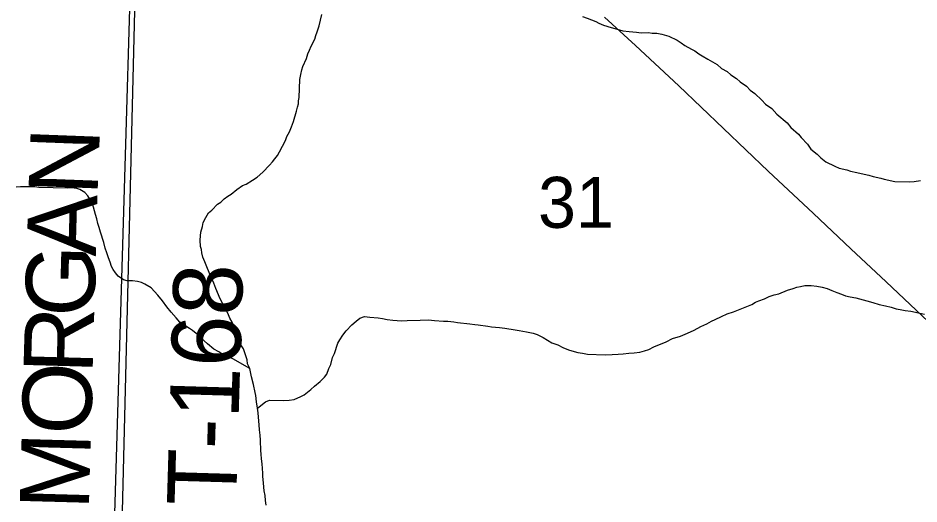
# Model space of a CAD drawing. Extents: x 0 to 34, y -2.3 to 22.
# Drawn here: x 2.383 to 3.123, y 14.692 to 15.091 of the extents above; entities that cross this region are included whole.
import ezdxf

# ---------------------------------------------------------------- set-up
doc = ezdxf.new("R2010")
doc.units = 0
for name, color, linetype in [('GM_X_Minor_River', 7, 'Continuous'), ('GM_X_Section', 7, 'Continuous'), ('GM_X_Section_Text', 7, 'Continuous'), ('GM_X_State_Route', 7, 'Continuous'), ('GM_X_Township', 7, 'Continuous'), ('GM_X_Township_Road', 7, 'Continuous'), ('GM_X_Township_Road_Text', 7, 'Continuous')]:
    doc.layers.add(name, color=color, linetype=linetype)

msp = doc.modelspace()

# ---------------------------------------------------------------- linework, layer by layer
at = {"layer": 'GM_X_Minor_River'}
for p, q in [((2.63081, 15.08452), (2.63298, 15.09395)), ((2.84693, 15.09212), (2.8507, 15.09087)), ((2.8507, 15.09087), (2.85784, 15.088)), ((2.62915, 15.07962), (2.63081, 15.08452)), ((2.85784, 15.088), (2.86046, 15.08678)), ((2.86046, 15.08678), (2.86422, 15.08515)), ((2.86422, 15.08515), (2.87062, 15.08306)), ((2.87062, 15.08306), (2.87741, 15.08133)), ((2.62707, 15.07361), (2.62792, 15.07662)), ((2.62792, 15.07662), (2.62915, 15.07962)), ((2.87741, 15.08133), (2.88005, 15.0805)), ((2.88005, 15.0805), (2.88536, 15.07996)), ((2.88536, 15.07996), (2.89142, 15.0794)), ((2.89142, 15.0794), (2.89521, 15.0789)), ((2.89521, 15.0789), (2.90129, 15.0791)), ((2.90129, 15.0791), (2.90432, 15.07863)), ((2.90432, 15.07863), (2.90812, 15.07852)), ((2.90812, 15.07852), (2.91228, 15.07764)), ((2.91228, 15.07764), (2.91793, 15.07595)), ((2.91793, 15.07595), (2.92468, 15.07271)), ((2.62264, 15.06462), (2.62425, 15.06799)), ((2.62425, 15.06799), (2.62707, 15.07361)), ((2.92468, 15.07271), (2.92804, 15.07071)), ((2.92804, 15.07071), (2.93101, 15.06834)), ((2.93101, 15.06834), (2.93663, 15.06551)), ((2.62016, 15.05786), (2.62141, 15.06162)), ((2.62141, 15.06162), (2.62264, 15.06462)), ((2.93663, 15.06551), (2.93925, 15.06391)), ((2.93925, 15.06391), (2.9426, 15.06153)), ((2.9426, 15.06153), (2.94521, 15.05994)), ((2.94521, 15.05994), (2.95007, 15.05713)), ((2.6173, 15.0511), (2.62016, 15.05786)), ((2.95007, 15.05713), (2.95755, 15.05273)), ((2.95755, 15.05273), (2.96126, 15.04958)), ((2.6156, 15.0447), (2.61647, 15.04847)), ((2.61647, 15.04847), (2.6173, 15.0511)), ((2.96126, 15.04958), (2.96575, 15.04717)), ((2.96575, 15.04717), (2.96871, 15.04442)), ((2.61429, 15.02574), (2.61472, 15.04054)), ((2.61472, 15.04054), (2.6156, 15.0447)), ((2.96871, 15.04442), (2.97356, 15.04123)), ((2.97356, 15.04123), (2.97652, 15.03848)), ((2.97652, 15.03848), (2.98174, 15.03491)), ((2.98174, 15.03491), (2.98469, 15.03178)), ((2.98469, 15.03178), (2.98841, 15.02901)), ((2.61376, 15.02044), (2.61383, 15.02309)), ((2.61383, 15.02309), (2.61429, 15.02574)), ((2.98841, 15.02901), (2.99434, 15.02352)), ((2.99434, 15.02352), (2.99729, 15.02039)), ((2.61206, 15.01441), (2.61292, 15.0178)), ((2.61292, 15.0178), (2.61376, 15.02044)), ((2.99729, 15.02039), (3.00251, 15.01682)), ((3.00251, 15.01682), (3.00655, 15.01214)), ((2.60954, 15.00613), (2.61206, 15.01441)), ((3.00655, 15.01214), (3.01509, 15.00504)), ((2.60625, 14.99749), (2.60789, 15.00161)), ((2.60789, 15.00161), (2.60954, 15.00613)), ((3.01509, 15.00504), (3.01802, 15.00115)), ((3.01802, 15.00115), (3.02432, 14.99565)), ((2.60301, 14.99036), (2.60425, 14.99375)), ((2.60425, 14.99375), (2.60625, 14.99749)), ((3.02432, 14.99565), (3.02652, 14.99292)), ((2.59818, 14.98101), (2.6006, 14.98588)), ((2.6006, 14.98588), (2.60301, 14.99036)), ((3.02652, 14.99292), (3.03169, 14.98745)), ((3.03169, 14.98745), (3.03461, 14.98318)), ((2.59657, 14.97802), (2.59818, 14.98101)), ((3.03461, 14.98318), (3.03981, 14.97923)), ((3.03981, 14.97923), (3.04276, 14.9761)), ((2.58988, 14.97024), (2.59224, 14.97283)), ((2.59224, 14.97283), (2.59422, 14.97543)), ((2.59422, 14.97543), (2.59657, 14.97802)), ((3.04276, 14.9761), (3.04686, 14.97294)), ((3.04686, 14.97294), (3.05435, 14.9693)), ((2.57971, 14.96028), (2.58439, 14.96432)), ((2.58439, 14.96432), (2.58988, 14.97024)), ((3.05435, 14.9693), (3.05773, 14.96768)), ((3.05773, 14.96768), (3.06415, 14.96635)), ((3.06415, 14.96635), (3.06715, 14.96512)), ((3.06715, 14.96512), (3.07245, 14.9642)), ((3.07245, 14.9642), (3.07585, 14.96334)), ((2.57081, 14.95447), (2.57584, 14.95774)), ((2.57584, 14.95774), (2.57971, 14.96028)), ((3.07585, 14.96334), (3.08227, 14.96201)), ((3.08227, 14.96201), (3.08565, 14.96076)), ((3.08565, 14.96076), (3.09208, 14.95943)), ((3.09208, 14.95943), (3.09471, 14.95859)), ((3.09471, 14.95859), (3.10341, 14.95682)), ((3.10341, 14.95682), (3.11556, 14.95645)), ((3.11556, 14.95645), (3.11937, 14.95672)), ((3.11937, 14.95672), (3.12472, 14.9577)), ((2.38525, 14.95241), (2.38182, 14.95214)), ((2.39704, 14.95244), (2.38525, 14.95241)), ((2.40044, 14.95196), (2.39704, 14.95244)), ((2.42399, 14.95126), (2.40044, 14.95196)), ((2.42704, 14.95154), (2.42399, 14.95126)), ((2.43159, 14.95103), (2.42704, 14.95154)), ((2.43422, 14.95019), (2.43159, 14.95103)), ((2.43833, 14.94779), (2.43422, 14.95019)), ((2.55841, 14.94648), (2.56308, 14.95014)), ((2.56308, 14.95014), (2.56773, 14.95342)), ((2.56773, 14.95342), (2.57081, 14.95447)), ((2.44054, 14.94506), (2.43833, 14.94779)), ((2.44416, 14.93888), (2.44054, 14.94506)), ((2.54986, 14.9399), (2.55259, 14.94248)), ((2.55259, 14.94248), (2.5557, 14.94467)), ((2.5557, 14.94467), (2.55841, 14.94648)), ((2.44521, 14.93581), (2.44416, 14.93888)), ((2.44626, 14.93273), (2.44521, 14.93581)), ((2.54245, 14.93328), (2.54715, 14.93808)), ((2.54715, 14.93808), (2.54986, 14.9399)), ((2.44693, 14.92967), (2.44626, 14.93273)), ((2.44798, 14.92622), (2.44693, 14.92967)), ((2.53532, 14.92324), (2.53771, 14.92735)), ((2.53771, 14.92735), (2.53972, 14.93108)), ((2.53972, 14.93108), (2.54245, 14.93328)), ((2.44901, 14.92239), (2.44798, 14.92622)), ((2.45005, 14.91894), (2.44901, 14.92239)), ((2.53357, 14.91531), (2.53484, 14.91983)), ((2.53484, 14.91983), (2.53532, 14.92324)), ((2.45108, 14.91511), (2.45005, 14.91894)), ((2.45387, 14.90667), (2.45108, 14.91511)), ((2.53299, 14.90849), (2.5331, 14.91229)), ((2.5331, 14.91229), (2.53357, 14.91531)), ((2.45488, 14.90208), (2.45387, 14.90667)), ((2.53323, 14.90354), (2.53299, 14.90849)), ((2.45629, 14.89824), (2.45488, 14.90208)), ((2.45769, 14.89402), (2.45629, 14.89824)), ((2.53391, 14.90086), (2.53323, 14.90354)), ((2.53421, 14.8982), (2.53391, 14.90086)), ((2.53525, 14.89474), (2.53421, 14.8982)), ((2.45911, 14.89056), (2.45769, 14.89402)), ((2.46015, 14.88711), (2.45911, 14.89056)), ((2.53666, 14.8909), (2.53525, 14.89474)), ((2.53844, 14.88667), (2.53666, 14.8909)), ((2.4616, 14.8844), (2.46015, 14.88711)), ((2.46342, 14.88169), (2.4616, 14.8844)), ((2.54021, 14.88206), (2.53844, 14.88667)), ((2.46562, 14.87897), (2.46342, 14.88169)), ((2.4701, 14.87617), (2.46562, 14.87897)), ((2.47312, 14.87532), (2.4701, 14.87617)), ((2.47729, 14.8752), (2.47312, 14.87532)), ((2.48146, 14.87469), (2.47729, 14.8752)), ((2.54199, 14.87783), (2.54021, 14.88206)), ((2.54414, 14.8732), (2.54199, 14.87783)), ((2.48486, 14.87383), (2.48146, 14.87469)), ((2.48748, 14.87261), (2.48486, 14.87383)), ((2.49271, 14.86942), (2.48748, 14.87261)), ((2.49825, 14.86356), (2.49271, 14.86942)), ((2.54591, 14.86897), (2.54414, 14.8732)), ((2.54947, 14.86051), (2.54591, 14.86897)), ((3.00838, 14.86467), (3.0153, 14.8675)), ((3.0153, 14.8675), (3.01991, 14.86889)), ((3.01991, 14.86889), (3.02298, 14.86993)), ((3.02298, 14.86993), (3.02603, 14.8706)), ((3.02603, 14.8706), (3.02948, 14.87126)), ((3.02948, 14.87126), (3.0348, 14.87148)), ((3.0348, 14.87148), (3.03935, 14.87097)), ((3.03935, 14.87097), (3.04389, 14.87007)), ((3.04389, 14.87007), (3.04803, 14.86881)), ((3.04803, 14.86881), (3.05178, 14.86717)), ((2.50191, 14.85889), (2.49825, 14.86356)), ((2.55163, 14.85626), (2.54947, 14.86051)), ((2.99186, 14.85871), (2.99648, 14.86047)), ((2.99648, 14.86047), (3.00033, 14.86225)), ((3.00033, 14.86225), (3.00455, 14.86364)), ((3.00455, 14.86364), (3.00838, 14.86467)), ((3.05178, 14.86717), (3.05592, 14.86553)), ((3.05592, 14.86553), (3.05968, 14.86428)), ((3.05968, 14.86428), (3.06307, 14.86304)), ((3.06307, 14.86304), (3.06684, 14.86217)), ((3.06684, 14.86217), (3.07138, 14.86127)), ((3.07138, 14.86127), (3.08043, 14.85872)), ((2.50557, 14.85384), (2.50191, 14.85889)), ((2.50924, 14.84955), (2.50557, 14.85384)), ((2.55342, 14.85241), (2.55163, 14.85626)), ((2.97646, 14.85195), (2.98185, 14.85407)), ((2.98185, 14.85407), (2.98608, 14.85584)), ((2.98608, 14.85584), (2.98917, 14.85764)), ((2.98917, 14.85764), (2.99186, 14.85871)), ((3.08043, 14.85872), (3.08533, 14.85744)), ((3.08533, 14.85744), (3.09061, 14.85576)), ((3.09061, 14.85576), (3.0959, 14.85484)), ((3.0959, 14.85484), (3.10043, 14.85357)), ((3.10043, 14.85357), (3.10457, 14.8523)), ((2.51329, 14.84487), (2.50924, 14.84955)), ((2.55559, 14.84855), (2.55342, 14.85241)), ((2.55738, 14.84469), (2.55559, 14.84855)), ((2.66418, 14.84455), (2.66802, 14.84595)), ((2.66802, 14.84595), (2.67219, 14.84545)), ((2.67219, 14.84545), (2.67902, 14.84486)), ((2.95607, 14.84344), (2.96109, 14.84595)), ((2.96109, 14.84595), (2.96571, 14.84809)), ((2.96571, 14.84809), (2.97108, 14.84983)), ((2.97108, 14.84983), (2.97646, 14.85195)), ((3.10457, 14.8523), (3.10798, 14.85182)), ((3.10798, 14.85182), (3.11213, 14.85094)), ((3.11213, 14.85094), (3.11668, 14.85042)), ((3.11668, 14.85042), (3.12801, 14.8478)), ((2.51623, 14.84136), (2.51329, 14.84487)), ((2.52033, 14.83858), (2.51623, 14.84136)), ((2.52406, 14.83619), (2.52033, 14.83858)), ((2.55918, 14.84122), (2.55738, 14.84469)), ((2.56061, 14.83814), (2.55918, 14.84122)), ((2.56203, 14.83468), (2.56061, 14.83814)), ((2.65286, 14.83425), (2.65756, 14.83904)), ((2.65756, 14.83904), (2.66107, 14.84198)), ((2.66107, 14.84198), (2.66418, 14.84455)), ((2.67902, 14.84486), (2.6828, 14.84437)), ((2.6828, 14.84437), (2.68658, 14.8435)), ((2.68658, 14.8435), (2.69112, 14.84298)), ((2.69112, 14.84298), (2.69833, 14.84239)), ((2.69833, 14.84239), (2.7029, 14.84263)), ((2.7029, 14.84263), (2.71355, 14.84307)), ((2.71355, 14.84307), (2.7204, 14.84325)), ((2.7204, 14.84325), (2.72533, 14.84272)), ((2.72533, 14.84272), (2.73291, 14.84212)), ((2.73291, 14.84212), (2.73633, 14.84201)), ((2.73633, 14.84201), (2.74126, 14.84149)), ((2.74126, 14.84149), (2.74428, 14.84102)), ((2.74428, 14.84102), (2.75452, 14.83995)), ((2.75452, 14.83995), (2.75868, 14.83945)), ((2.75868, 14.83945), (2.76133, 14.83899)), ((2.76133, 14.83899), (2.76928, 14.83799)), ((2.76928, 14.83799), (2.77231, 14.83752)), ((2.94412, 14.83771), (2.94913, 14.83984)), ((2.94913, 14.83984), (2.95299, 14.84201)), ((2.95299, 14.84201), (2.95607, 14.84344)), ((2.52668, 14.83459), (2.52406, 14.83619)), ((2.53373, 14.82868), (2.52668, 14.83459)), ((2.56383, 14.8312), (2.56203, 14.83468)), ((2.56632, 14.82543), (2.56383, 14.8312)), ((2.64771, 14.8268), (2.6501, 14.83053)), ((2.6501, 14.83053), (2.65286, 14.83425)), ((2.77231, 14.83752), (2.77875, 14.83695)), ((2.77875, 14.83695), (2.7833, 14.83643)), ((2.7833, 14.83643), (2.79162, 14.83504)), ((2.79162, 14.83504), (2.79503, 14.83456)), ((2.79503, 14.83456), (2.80107, 14.83324)), ((2.80107, 14.83324), (2.80637, 14.83233)), ((2.80637, 14.83233), (2.80975, 14.83108)), ((2.80975, 14.83108), (2.81463, 14.82866)), ((2.92755, 14.82985), (2.93333, 14.83234)), ((2.93333, 14.83234), (2.93872, 14.83484)), ((2.93872, 14.83484), (2.94412, 14.83771)), ((2.53631, 14.82595), (2.53373, 14.82868)), ((2.5389, 14.82359), (2.53631, 14.82595)), ((2.5441, 14.81925), (2.5389, 14.82359)), ((2.56625, 14.82277), (2.56632, 14.82543)), ((2.6432, 14.81554), (2.64611, 14.82419)), ((2.64611, 14.82419), (2.64771, 14.8268)), ((2.81463, 14.82866), (2.81837, 14.82665)), ((2.81837, 14.82665), (2.82172, 14.82427)), ((2.82172, 14.82427), (2.82661, 14.8226)), ((2.90563, 14.82101), (2.91564, 14.82527)), ((2.91564, 14.82527), (2.92103, 14.82777)), ((2.92103, 14.82777), (2.92755, 14.82985)), ((2.54821, 14.81685), (2.5441, 14.81925)), ((2.55083, 14.81525), (2.54821, 14.81685)), ((2.56843, 14.81929), (2.56625, 14.82277)), ((2.57159, 14.81046), (2.56843, 14.81929)), ((2.64158, 14.81217), (2.6432, 14.81554)), ((2.82661, 14.8226), (2.83074, 14.82058)), ((2.83074, 14.82058), (2.83562, 14.81853)), ((2.83562, 14.81853), (2.84014, 14.81726)), ((2.84014, 14.81726), (2.84316, 14.81641)), ((2.84316, 14.81641), (2.84695, 14.81592)), ((2.84695, 14.81592), (2.85111, 14.81503)), ((2.88038, 14.8153), (2.88496, 14.81592)), ((2.88496, 14.81592), (2.88953, 14.81617)), ((2.88953, 14.81617), (2.89411, 14.81679)), ((2.89411, 14.81679), (2.89794, 14.81782)), ((2.89794, 14.81782), (2.90139, 14.81885)), ((2.90139, 14.81885), (2.90563, 14.82101)), ((2.55345, 14.81404), (2.55083, 14.81525)), ((2.55721, 14.81241), (2.55345, 14.81404)), ((2.55983, 14.81119), (2.55721, 14.81241)), ((2.57367, 14.80318), (2.55983, 14.81119)), ((2.57188, 14.80703), (2.57159, 14.81046)), ((2.64028, 14.80651), (2.64158, 14.81217)), ((2.85111, 14.81503), (2.86554, 14.8146)), ((2.86554, 14.8146), (2.87124, 14.81481)), ((2.87124, 14.81481), (2.87619, 14.81505)), ((2.87619, 14.81505), (2.88038, 14.8153)), ((2.57367, 14.80318), (2.57188, 14.80703)), ((2.57499, 14.7963), (2.57367, 14.80318)), ((2.63701, 14.79863), (2.63866, 14.80314)), ((2.63866, 14.80314), (2.64028, 14.80651)), ((2.57671, 14.79017), (2.57499, 14.7963)), ((2.63152, 14.79271), (2.63503, 14.79603)), ((2.63503, 14.79603), (2.63701, 14.79863)), ((2.57804, 14.78367), (2.57671, 14.79017)), ((2.61828, 14.78171), (2.62373, 14.7861)), ((2.62373, 14.7861), (2.62684, 14.78867)), ((2.62684, 14.78867), (2.63152, 14.79271)), ((2.57873, 14.78099), (2.57804, 14.78367)), ((2.57934, 14.77603), (2.57873, 14.78099)), ((2.61018, 14.77777), (2.61557, 14.78027)), ((2.61557, 14.78027), (2.61828, 14.78171)), ((2.57995, 14.77069), (2.57934, 14.77603)), ((2.57995, 14.77069), (2.58656, 14.77582)), ((2.58656, 14.77582), (2.59002, 14.77723)), ((2.59002, 14.77723), (2.60142, 14.77689)), ((2.60142, 14.77689), (2.60598, 14.77714)), ((2.60598, 14.77714), (2.61018, 14.77777)), ((2.5806, 14.76688), (2.57995, 14.77069)), ((2.58116, 14.76002), (2.5806, 14.76688)), ((2.58146, 14.75697), (2.58116, 14.76002)), ((2.58171, 14.75278), (2.58146, 14.75697)), ((2.58236, 14.74859), (2.58171, 14.75278)), ((2.58261, 14.7444), (2.58236, 14.74859)), ((2.58253, 14.74136), (2.58261, 14.7444)), ((2.58283, 14.73869), (2.58253, 14.74136)), ((2.58275, 14.73604), (2.58283, 14.73869)), ((2.58304, 14.73299), (2.58275, 14.73604)), ((2.58331, 14.72918), (2.58304, 14.73299)), ((2.58395, 14.72498), (2.58331, 14.72918)), ((2.58449, 14.71737), (2.58395, 14.72498)), ((2.58442, 14.71471), (2.58449, 14.71737)), ((2.58502, 14.70937), (2.58442, 14.71471)), ((2.58531, 14.70595), (2.58502, 14.70937)), ((2.5856, 14.7029), (2.58531, 14.70595)), ((2.58625, 14.69908), (2.5856, 14.7029)), ((2.58651, 14.69489), (2.58625, 14.69908)), ((2.58716, 14.69107), (2.58651, 14.69489))]:
    msp.add_line(p, q, dxfattribs=at)
at = {"layer": 'GM_X_Section'}
msp.add_line((2.46448, 14.49183), (2.48719, 15.41263), dxfattribs=at)
msp.add_line((2.46448, 14.49183), (2.48719, 15.41263), dxfattribs=at)
at = {"layer": 'GM_X_State_Route'}
for p, q in [((2.86514, 15.09159), (2.89059, 15.0685)), ((2.89059, 15.0685), (2.92609, 15.03525)), ((2.92609, 15.03525), (2.96272, 15.00027)), ((2.96272, 15.00027), (2.99955, 14.96528)), ((2.99955, 14.96528), (3.0368, 14.9304)), ((3.0368, 14.9304), (3.06727, 14.90157)), ((3.06727, 14.90157), (3.09651, 14.87448)), ((3.09651, 14.87448), (3.13078, 14.84175))]:
    msp.add_line(p, q, dxfattribs=at)
at = {"layer": 'GM_X_Township'}
for p, q in [((2.47178, 14.98755), (2.4855, 15.44815)), ((2.47178, 14.98755), (2.4855, 15.44815)), ((2.45706, 14.48507), (2.47178, 14.98755)), ((2.45706, 14.48507), (2.47178, 14.98755))]:
    msp.add_line(p, q, dxfattribs=at)
at = {"layer": 'GM_X_Township_Road'}
for p, q in [((2.47178, 14.98755), (2.4855, 15.44815)), ((2.45706, 14.48507), (2.47178, 14.98755))]:
    msp.add_line(p, q, dxfattribs=at)

# ---------------------------------------------------------------- texts
at = {"layer": 'GM_X_Section_Text'}
msp.add_text('31', height=0.041856, rotation=0.00001, dxfattribs=at).set_placement((2.81048, 14.91874))
at = {"layer": 'GM_X_Township_Road_Text'}
for s, height, rotation, p in [('N', 0.05682, 87.83569, (2.44859, 14.94487)), ('A', 0.05682, 88.41335, (2.44722, 14.89504)), ('G', 0.05682, 88.41752, (2.44583, 14.84506)), ('T-168', 0.056818, 88.31543, (2.56239, 14.68994)), ('R', 0.05682, 88.41715, (2.44454, 14.79842)), ('O', 0.05682, 88.4179, (2.44317, 14.74844)), ('M', 0.05682, 88.41816, (2.44146, 14.68679))]:
    msp.add_text(s, height=height, rotation=rotation, dxfattribs=at).set_placement(p)

doc.saveas('drawing.dxf')
